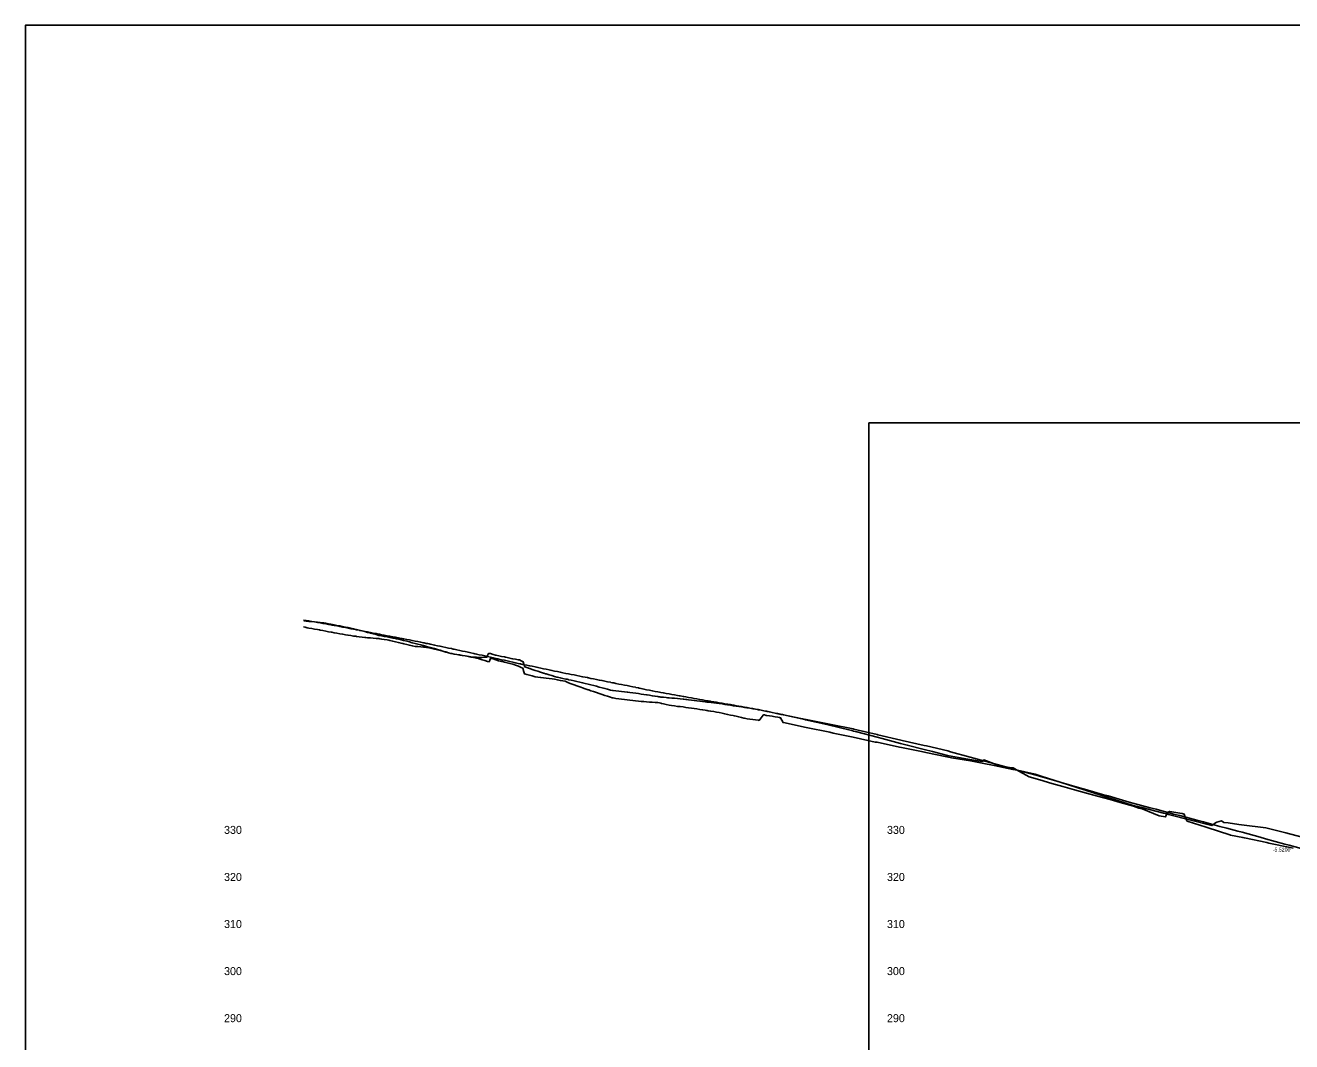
# Model space of a CAD drawing. Extents: x 2230305 to 2233905, y 1078764 to 1080964.
# Drawn here: x 2230305 to 2231649, y 1079884 to 1080964 of the extents above; entities that cross this region are included whole.
import ezdxf

# ---------------------------------------------------------------- set-up
doc = ezdxf.new("R2010")
doc.units = 0
for name, color, linetype in [('BR_EXIST_GROUND_LT', 7, 'Continuous'), ('BR_EXIST_GROUND_RT', 7, 'Continuous'), ('BR_USER NOTES', 7, 'Continuous'), ('RD_DDB_ElevTX', 7, 'Continuous'), ('RD_DDB_Profile_EX', 7, 'Continuous'), ('RD_SHT_IplotShp', 7, 'Continuous'), ('RD_SHT_ShtClip', 7, 'Continuous')]:
    doc.layers.add(name, color=color, linetype=linetype)

msp = doc.modelspace()

# ---------------------------------------------------------------- linework, layer by layer
at = {"layer": 'BR_EXIST_GROUND_LT'}
msp.add_lwpolyline([(2230600.2, 1080324.6), (2230601.8, 1080324.3), (2230603, 1080324), (2230604, 1080323.8), (2230605.9, 1080323.4), (2230608.9, 1080322.9), (2230611.9, 1080322.3), (2230614.8, 1080321.9), (2230616.9, 1080321.5), (2230617.8, 1080321.3), (2230620.7, 1080320.7), (2230623.7, 1080320.2), (2230626.7, 1080319.6), (2230629.6, 1080319.1), (2230630.2, 1080319), (2230632.6, 1080318.5), (2230635.6, 1080317.9), (2230638.5, 1080317.4), (2230641.7, 1080316.8), (2230644.5, 1080316.4), (2230647.4, 1080315.9), (2230650.4, 1080315.4), (2230653.3, 1080315), (2230655.6, 1080314.7), (2230656.3, 1080314.6), (2230659.3, 1080314.2), (2230662.2, 1080313.8), (2230665.2, 1080313.5), (2230666.2, 1080313.4), (2230668.2, 1080313.2), (2230671.1, 1080312.9), (2230674.1, 1080312.6), (2230677.1, 1080312.4), (2230680, 1080312.2), (2230681.1, 1080312.1), (2230683, 1080311.8), (2230685.9, 1080311.3), (2230688.9, 1080310.9), (2230690.7, 1080310.6), (2230691.9, 1080310.3), (2230694.8, 1080309.5), (2230697.8, 1080308.8), (2230700.8, 1080308), (2230703.7, 1080307.3), (2230705.4, 1080306.9), (2230706.7, 1080306.6), (2230709.7, 1080305.9), (2230712.6, 1080305.2), (2230715.6, 1080304.6), (2230718.5, 1080304), (2230721.5, 1080303.7), (2230724.5, 1080303.4), (2230727.4, 1080303.2), (2230730.4, 1080303), (2230730.9, 1080302.9), (2230731.4, 1080302.8), (2230733.4, 1080302.3), (2230736.3, 1080301.7), (2230739.3, 1080301), (2230742.3, 1080300.4), (2230745.2, 1080299.7), (2230746.4, 1080299.5), (2230748.2, 1080298.9), (2230751.1, 1080298), (2230754.1, 1080297.2), (2230757.1, 1080296.3), (2230760, 1080295.8), (2230763, 1080295.3), (2230766, 1080294.9), (2230768.9, 1080294.4), (2230771.9, 1080294), (2230773.7, 1080293.7), (2230774.9, 1080293.4), (2230777.8, 1080292.7), (2230780.8, 1080292), (2230782.3, 1080291.7), (2230783.8, 1080291.4), (2230785.8, 1080291), (2230786.7, 1080290.8), (2230789.7, 1080289.8), (2230792.6, 1080289), (2230795.6, 1080288.1), (2230797.1, 1080287.7), (2230798.5, 1080291.2), (2230799.9, 1080291.2), (2230801.5, 1080290.7), (2230804.5, 1080289.6), (2230807.1, 1080288.8), (2230807.5, 1080288.7), (2230810.4, 1080288), (2230811.3, 1080287.8), (2230813.4, 1080287.3), (2230816.4, 1080286.5), (2230819.3, 1080285.7), (2230822.3, 1080285), (2230823.6, 1080284.6), (2230825.2, 1080284.1), (2230828.3, 1080283), (2230831.2, 1080281.7), (2230833.1, 1080280.9), (2230834.1, 1080277.1), (2230834.8, 1080274.7), (2230837.1, 1080274.1), (2230840.1, 1080273.3), (2230843, 1080272.6), (2230846.1, 1080271.8), (2230849, 1080271.4), (2230851.9, 1080271), (2230852.2, 1080270.9), (2230854.9, 1080270.6), (2230857.8, 1080270.2), (2230860.8, 1080269.8), (2230864.1, 1080269.5), (2230866.7, 1080269), (2230869.7, 1080268.4), (2230872.7, 1080267.9), (2230875.6, 1080267.3), (2230878, 1080266.9), (2230878.6, 1080266.6), (2230881.6, 1080265.4), (2230884.5, 1080264.3), (2230887.5, 1080263.1), (2230890.4, 1080262), (2230893.4, 1080260.9), (2230894.6, 1080260.5), (2230896.4, 1080259.9), (2230899.3, 1080258.9), (2230902.3, 1080258), (2230903.2, 1080257.7), (2230905.3, 1080256.9), (2230908.2, 1080255.9), (2230911.2, 1080254.9), (2230914.2, 1080253.9), (2230917.1, 1080252.9), (2230920.1, 1080251.9), (2230923, 1080251), (2230926, 1080250.1), (2230927.8, 1080249.5), (2230928.5, 1080249.3), (2230929, 1080249.3), (2230931.9, 1080248.8), (2230934.9, 1080248.3), (2230937.8, 1080247.9), (2230940.8, 1080247.6), (2230943.8, 1080247.2), (2230946.8, 1080246.9), (2230949.7, 1080246.5), (2230952.8, 1080246.1), (2230955.7, 1080245.8), (2230958.6, 1080245.5), (2230961.6, 1080245.3), (2230964.5, 1080245), (2230967.5, 1080244.8), (2230970.5, 1080244.6), (2230973.4, 1080244.4), (2230976.4, 1080244.2), (2230978.1, 1080244.1), (2230979.4, 1080243.7), (2230980.4, 1080243.4), (2230982.3, 1080243), (2230985.3, 1080242.3), (2230988.3, 1080241.7), (2230991, 1080241.1), (2230994.2, 1080240.7), (2230997.1, 1080240.3), (2231000.1, 1080240), (2231003.1, 1080239.6), (2231006, 1080239.2), (2231009, 1080238.8), (2231012, 1080238.4), (2231014.9, 1080238), (2231017.9, 1080237.5), (2231020.9, 1080237.1), (2231023.8, 1080236.6), (2231024.3, 1080236.6), (2231026.8, 1080236.2), (2231028.2, 1080236), (2231028.7, 1080235.9), (2231029.7, 1080235.7), (2231032.2, 1080235.2), (2231032.7, 1080235.2), (2231035.9, 1080234.7), (2231038.6, 1080234.2), (2231041.6, 1080233.6), (2231044.6, 1080233), (2231047.5, 1080232.3), (2231050.5, 1080231.7), (2231053.5, 1080231), (2231056.4, 1080230.4), (2231057.7, 1080230.1), (2231059.4, 1080229.8), (2231062.3, 1080229), (2231065.3, 1080228.3), (2231067.8, 1080227.6), (2231068.3, 1080227.6), (2231071.2, 1080227.1), (2231074.2, 1080226.7), (2231077.2, 1080226.3), (2231080.1, 1080225.9), (2231083.1, 1080225.5), (2231083.9, 1080225.4), (2231086.1, 1080228.2), (2231088.2, 1080231), (2231089, 1080231.2), (2231089.8, 1080231.4), (2231091.4, 1080230.7), (2231092, 1080230.6), (2231094.9, 1080230.2), (2231097.9, 1080229.7), (2231099.3, 1080229.5), (2231100.9, 1080229.2), (2231103.8, 1080228.7), (2231105.7, 1080228.4), (2231106.1, 1080228.1), (2231106.8, 1080228.2), (2231109.3, 1080223.1), (2231109.8, 1080223), (2231134, 1080217.9), (2231158.9, 1080212.7), (2231162.5, 1080211.9), (2231183.9, 1080207.5), (2231207.1, 1080202.4), (2231208.2, 1080202.3), (2231209.2, 1080202.1), (2231233.1, 1080197), (2231235, 1080196.6), (2231258.1, 1080191.8), (2231260.8, 1080191.3), (2231283.2, 1080186.6), (2231283.5, 1080186.5), (2231288.2, 1080185.6), (2231308.5, 1080182.3), (2231320.9, 1080179.8), (2231333.5, 1080177.6), (2231353.2, 1080173.3), (2231358.4, 1080172.4), (2231377.2, 1080168.2), (2231383.4, 1080166.2), (2231404.8, 1080159.5), (2231429.2, 1080151.7), (2231429.9, 1080151.5), (2231431.1, 1080151), (2231455.7, 1080143.2), (2231480, 1080135.4), (2231490.4, 1080132.8), (2231513.5, 1080126.8), (2231517, 1080126), (2231518.7, 1080125.5), (2231542.3, 1080119.4), (2231564.8, 1080113.7), (2231568.6, 1080116.5), (2231569.9, 1080117.4), (2231575.1, 1080118.8), (2231577.5, 1080116.8), (2231582.1, 1080116.4), (2231593.4, 1080114.9), (2231596.1, 1080114.6), (2231621.9, 1080111.4), (2231643.1, 1080106), (2231647, 1080104.8), (2231665, 1080100.1)], dxfattribs=at)
at = {"layer": 'BR_EXIST_GROUND_RT'}
msp.add_lwpolyline([(2230600.6, 1080331.1), (2230603, 1080330.9), (2230604.4, 1080330.7), (2230605.9, 1080330.5), (2230608.9, 1080330.3), (2230611.9, 1080330), (2230614.8, 1080329.7), (2230617.8, 1080329.4), (2230620.7, 1080329), (2230621.8, 1080328.9), (2230623.7, 1080328.6), (2230626.7, 1080328), (2230628.9, 1080327.6), (2230629.6, 1080327.4), (2230630.3, 1080327.3), (2230630.8, 1080327.2), (2230632.6, 1080326.9), (2230635.6, 1080326.3), (2230638.5, 1080325.8), (2230639.6, 1080325.6), (2230641.5, 1080325.1), (2230644.5, 1080324.5), (2230647.4, 1080323.9), (2230650.4, 1080323.2), (2230653.3, 1080322.5), (2230655.3, 1080322), (2230656.3, 1080321.8), (2230659.3, 1080321.1), (2230662.2, 1080320.4), (2230665.2, 1080319.7), (2230668.2, 1080318.9), (2230669.4, 1080318.6), (2230671.1, 1080318.2), (2230674.1, 1080317.4), (2230677.1, 1080316.5), (2230680, 1080315.7), (2230680.5, 1080315.6), (2230681.6, 1080315.4), (2230683, 1080315.2), (2230685.9, 1080314.6), (2230688.9, 1080314), (2230691.9, 1080313.4), (2230694.8, 1080312.8), (2230697.8, 1080312.2), (2230699, 1080311.9), (2230700.8, 1080311.5), (2230703.7, 1080310.8), (2230706.2, 1080310.2), (2230706.7, 1080310.1), (2230709.7, 1080309.4), (2230712.6, 1080308.7), (2230715.6, 1080307.9), (2230718.5, 1080307.2), (2230721.5, 1080306.4), (2230724.5, 1080305.7), (2230726.8, 1080305), (2230727.4, 1080304.9), (2230730.7, 1080303.9), (2230733, 1080303.3), (2230733.4, 1080303.2), (2230736.3, 1080302.4), (2230739.3, 1080301.6), (2230742.3, 1080300.8), (2230745.2, 1080299.9), (2230748.2, 1080299), (2230751.1, 1080298.1), (2230754.1, 1080297.2), (2230756.7, 1080296.4), (2230757.1, 1080296.4), (2230757.5, 1080296.3), (2230760, 1080295.8), (2230763, 1080295.3), (2230766, 1080294.8), (2230768.9, 1080294.3), (2230771.9, 1080293.8), (2230774.9, 1080293.4), (2230776, 1080293.2), (2230777.8, 1080292.9), (2230780.8, 1080292.6), (2230782.1, 1080292.4), (2230783.8, 1080292.4), (2230786.7, 1080292.3), (2230788.3, 1080292.2), (2230789.7, 1080292.3), (2230792.6, 1080292.4), (2230794.9, 1080292.6), (2230795.6, 1080294.2), (2230796.5, 1080296.3), (2230798.3, 1080296.4), (2230798.6, 1080296.3), (2230801.5, 1080295.5), (2230803.8, 1080294.8), (2230804.5, 1080294.7), (2230807.5, 1080294), (2230810.4, 1080293.4), (2230813.4, 1080292.8), (2230814.5, 1080292.5), (2230816.4, 1080292.1), (2230819.3, 1080291.3), (2230820.6, 1080291), (2230822.3, 1080290.7), (2230825.2, 1080290.3), (2230828.2, 1080289.8), (2230829.3, 1080289.6), (2230831.2, 1080288.7), (2230833.2, 1080287.7), (2230834.1, 1080285), (2230835.1, 1080282.3), (2230837.1, 1080281.6), (2230840.1, 1080280.5), (2230840.4, 1080280.4), (2230843, 1080279.5), (2230846, 1080278.5), (2230849, 1080277.5), (2230851.9, 1080276.6), (2230854.9, 1080275.6), (2230855.4, 1080275.5), (2230857.2, 1080274.9), (2230857.8, 1080274.7), (2230860.8, 1080273.8), (2230863.8, 1080272.9), (2230866.7, 1080272.1), (2230869, 1080271.4), (2230869.7, 1080271.3), (2230872.7, 1080270.6), (2230875.6, 1080269.9), (2230878.6, 1080269.3), (2230879.9, 1080269), (2230881.1, 1080268.7), (2230881.6, 1080268.6), (2230884.5, 1080268), (2230887.5, 1080267.3), (2230890.4, 1080266.6), (2230893.4, 1080266), (2230896.4, 1080265.3), (2230899.3, 1080264.6), (2230902.3, 1080263.9), (2230903.7, 1080263.5), (2230905.3, 1080263.1), (2230908.4, 1080262.3), (2230911.2, 1080261.6), (2230914.2, 1080260.8), (2230917.1, 1080260), (2230920.1, 1080259.3), (2230923, 1080258.5), (2230926, 1080257.6), (2230928.4, 1080257), (2230929, 1080257), (2230931.9, 1080256.7), (2230934.9, 1080256.4), (2230937.9, 1080256.1), (2230940.8, 1080255.7), (2230943.8, 1080255.4), (2230944.4, 1080255.3), (2230946.8, 1080255), (2230949.7, 1080254.6), (2230952.9, 1080254.2), (2230955.7, 1080253.8), (2230958.6, 1080253.4), (2230961.6, 1080253), (2230964.5, 1080252.6), (2230964.9, 1080252.5), (2230967.5, 1080252.1), (2230970.5, 1080251.6), (2230973.4, 1080251.1), (2230976.4, 1080250.6), (2230977.4, 1080250.4), (2230978.6, 1080250.3), (2230979.4, 1080250.2), (2230982.3, 1080250), (2230985.3, 1080249.7), (2230986.8, 1080249.5), (2230988.3, 1080249.4), (2230991.2, 1080249.1), (2230994.2, 1080248.9), (2230997.1, 1080248.6), (2231000.1, 1080248.3), (2231003.1, 1080247.9), (2231004, 1080247.9), (2231006, 1080247.6), (2231007.3, 1080247.5), (2231009, 1080247.3), (2231012, 1080246.9), (2231014.9, 1080246.6), (2231017.9, 1080246.2), (2231020.9, 1080245.8), (2231023.8, 1080245.4), (2231026.8, 1080245.1), (2231028.5, 1080244.8), (2231028.9, 1080244.8), (2231029.7, 1080244.7), (2231032.9, 1080244.3), (2231033.9, 1080244.2), (2231035.7, 1080244), (2231038.6, 1080243.7), (2231039.3, 1080243.6), (2231041.6, 1080243.2), (2231044.6, 1080242.8), (2231047.5, 1080242.3), (2231050.5, 1080241.9), (2231053.5, 1080241.4), (2231056.4, 1080241), (2231057.1, 1080240.9), (2231057.8, 1080240.8), (2231059.4, 1080240.5), (2231062.3, 1080240.1), (2231065.3, 1080239.6), (2231068.3, 1080239.2), (2231071.2, 1080238.7), (2231074.2, 1080238.3), (2231077.2, 1080237.8), (2231080.1, 1080237.3), (2231082, 1080237.1), (2231083.1, 1080236.8), (2231086.1, 1080236.2), (2231089, 1080235.5), (2231092, 1080234.9), (2231094.9, 1080234.3), (2231097.9, 1080233.6), (2231100.9, 1080233), (2231103.8, 1080232.4), (2231107.1, 1080231.7), (2231109.8, 1080231.1), (2231132.3, 1080226.3), (2231133.1, 1080226.1), (2231155.8, 1080220.9), (2231157.3, 1080220.5), (2231179.3, 1080215.4), (2231182.3, 1080214.6), (2231184.3, 1080214.1), (2231187.8, 1080213.2), (2231209.2, 1080207.5), (2231214.6, 1080206.2), (2231234.2, 1080201), (2231241.3, 1080199.2), (2231259.2, 1080194.5), (2231267.9, 1080192.3), (2231284.1, 1080188), (2231288, 1080187.3), (2231295.5, 1080186), (2231305.5, 1080184.3), (2231320.6, 1080181.7), (2231321.6, 1080182.2), (2231322.7, 1080183.5), (2231335.6, 1080178.5), (2231342.4, 1080176.6), (2231349.6, 1080175.5), (2231353.6, 1080174.8), (2231357.1, 1080172.8), (2231370.7, 1080165.4), (2231382.1, 1080162.1), (2231394.9, 1080158.4), (2231406.6, 1080155.2), (2231418.9, 1080151.7), (2231431.6, 1080148.2), (2231443.1, 1080145), (2231456.6, 1080141.2), (2231467.2, 1080138.2), (2231481.5, 1080134.3), (2231487, 1080132.1), (2231490.8, 1080131.4), (2231508.8, 1080124), (2231515.6, 1080122.8), (2231517.7, 1080127.7), (2231518.1, 1080127.9), (2231519.9, 1080128.6), (2231522.2, 1080128.2), (2231530.6, 1080126.9), (2231533.2, 1080126.6), (2231534.3, 1080126.1), (2231535.3, 1080125.9), (2231536.7, 1080121.6), (2231538.6, 1080118.5), (2231558.6, 1080111.9), (2231559.6, 1080111.7), (2231583.7, 1080103.8), (2231584.4, 1080103.6), (2231597.6, 1080100.9), (2231598.1, 1080100.8), (2231599.3, 1080100.5), (2231623, 1080095.6), (2231625.2, 1080095.1), (2231648, 1080090.3), (2231651.1, 1080089.7)], dxfattribs=at)
at = {"layer": 'RD_DDB_Profile_EX'}
msp.add_lwpolyline([(2230600, 1080332), (2230603, 1080331.5), (2230604.3, 1080331.3), (2230605.9, 1080331), (2230608.9, 1080330.5), (2230611.9, 1080330), (2230614.8, 1080329.4), (2230617.8, 1080328.9), (2230620.7, 1080328.4), (2230623.7, 1080327.9), (2230626.7, 1080327.3), (2230629.6, 1080326.8), (2230630.6, 1080326.6), (2230632.6, 1080326.2), (2230635.6, 1080325.7), (2230638.5, 1080325.1), (2230641.5, 1080324.5), (2230644.5, 1080324), (2230647.4, 1080323.4), (2230650.4, 1080322.8), (2230653.3, 1080322.3), (2230655.5, 1080321.8), (2230656.3, 1080321.7), (2230659.3, 1080321.1), (2230659.7, 1080321), (2230662.2, 1080320.5), (2230665.2, 1080319.9), (2230668.2, 1080319.3), (2230671.1, 1080318.8), (2230674.1, 1080318.2), (2230677.1, 1080317.6), (2230679.3, 1080317.1), (2230680, 1080317), (2230680.8, 1080316.8), (2230683, 1080316.4), (2230685.9, 1080315.9), (2230688.9, 1080315.3), (2230691.9, 1080314.7), (2230694.8, 1080314.2), (2230697.8, 1080313.6), (2230700.8, 1080313.1), (2230703.7, 1080312.5), (2230704.5, 1080312.4), (2230705.8, 1080312.1), (2230706.7, 1080311.9), (2230709.7, 1080311.3), (2230712.6, 1080310.8), (2230715.6, 1080310.2), (2230718.5, 1080309.6), (2230721.5, 1080309), (2230724.5, 1080308.4), (2230727.4, 1080307.9), (2230728.3, 1080307.7), (2230730.4, 1080307.2), (2230730.8, 1080307.1), (2230732.2, 1080306.9), (2230733.4, 1080306.6), (2230734.6, 1080306.3), (2230736.3, 1080306), (2230739.3, 1080305.4), (2230742.3, 1080304.7), (2230745.2, 1080304.1), (2230748.2, 1080303.5), (2230751.1, 1080302.9), (2230754.1, 1080302.2), (2230757.1, 1080301.6), (2230759, 1080301.2), (2230760, 1080301), (2230763, 1080300.3), (2230766, 1080299.7), (2230768.9, 1080299), (2230771.9, 1080298.4), (2230774.9, 1080297.7), (2230777.8, 1080297.1), (2230780.8, 1080296.4), (2230782.1, 1080296.1), (2230783.8, 1080295.8), (2230786.7, 1080295.1), (2230789.7, 1080294.5), (2230792.6, 1080293.8), (2230795.6, 1080293.2), (2230798.6, 1080292.5), (2230801.5, 1080291.9), (2230804.5, 1080291.2), (2230805.6, 1080290.9), (2230806.4, 1080290.8), (2230807.5, 1080290.5), (2230810.4, 1080289.8), (2230813.4, 1080289.2), (2230816.4, 1080288.5), (2230819.3, 1080287.8), (2230822.3, 1080287.2), (2230825.2, 1080286.5), (2230828.2, 1080285.8), (2230830, 1080285.4), (2230830.5, 1080285.3), (2230831.2, 1080285.1), (2230834.1, 1080284.5), (2230837.1, 1080284), (2230840.1, 1080283.4), (2230843, 1080282.8), (2230846, 1080282.2), (2230849, 1080281.6), (2230852.1, 1080280.9), (2230853.5, 1080280.6), (2230854.9, 1080280.3), (2230857.8, 1080279.7), (2230860.8, 1080279.1), (2230863.8, 1080278.5), (2230866.7, 1080277.8), (2230869.7, 1080277.2), (2230872.7, 1080276.6), (2230875.6, 1080275.9), (2230878.5, 1080275.3), (2230878.5, 1080275.3), (2230881.6, 1080274.7), (2230884.5, 1080274.1), (2230887.5, 1080273.6), (2230890.4, 1080273), (2230893.4, 1080272.4), (2230896.4, 1080271.8), (2230899.3, 1080271.2), (2230901.5, 1080270.8), (2230902.3, 1080270.6), (2230902.9, 1080270.5), (2230905.3, 1080270), (2230908.2, 1080269.4), (2230911.2, 1080268.8), (2230914.2, 1080268.2), (2230917.1, 1080267.6), (2230920.1, 1080267), (2230923, 1080266.4), (2230926, 1080265.8), (2230926.4, 1080265.7), (2230928.1, 1080265.4), (2230929, 1080265.2), (2230929.8, 1080265.1), (2230931.9, 1080264.6), (2230934.9, 1080264), (2230937.9, 1080263.4), (2230940.8, 1080262.9), (2230943.8, 1080262.3), (2230946.8, 1080261.7), (2230949.7, 1080261.1), (2230952.7, 1080260.5), (2230953.1, 1080260.4), (2230955.7, 1080259.8), (2230956.7, 1080259.6), (2230958.6, 1080259.2), (2230961.6, 1080258.6), (2230964.5, 1080258), (2230967.5, 1080257.4), (2230970.5, 1080256.8), (2230973.4, 1080256.2), (2230976.4, 1080255.6), (2230978.3, 1080255.2), (2230979.4, 1080255), (2230982.3, 1080254.5), (2230985.3, 1080254), (2230988.3, 1080253.5), (2230991.2, 1080252.9), (2230994.2, 1080252.4), (2230997.1, 1080251.9), (2230999, 1080251.6), (2231000.1, 1080251.4), (2231003.1, 1080250.9), (2231004.1, 1080250.7), (2231006, 1080250.4), (2231009, 1080249.8), (2231012, 1080249.3), (2231014.9, 1080248.8), (2231017.9, 1080248.2), (2231020.9, 1080247.7), (2231023.8, 1080247.2), (2231026.8, 1080246.6), (2231029.1, 1080246.2), (2231029.8, 1080246.1), (2231032.1, 1080245.7), (2231032.7, 1080245.6), (2231035.7, 1080245.1), (2231038.6, 1080244.6), (2231041.6, 1080244.1), (2231044.6, 1080243.6), (2231047.5, 1080243.1), (2231050.6, 1080242.6), (2231053.5, 1080242.1), (2231056.4, 1080241.5), (2231057.1, 1080241.4), (2231059.4, 1080241), (2231062.3, 1080240.5), (2231065.3, 1080240), (2231068.3, 1080239.5), (2231071.2, 1080238.9), (2231074.2, 1080238.4), (2231076, 1080238.1), (2231077.2, 1080237.9), (2231080.1, 1080237.3), (2231082.1, 1080237), (2231083.3, 1080236.7), (2231083.9, 1080236.6), (2231086.1, 1080236.2), (2231089, 1080235.6), (2231092, 1080235), (2231094.9, 1080234.4), (2231097.9, 1080233.8), (2231100.9, 1080233.2), (2231103.8, 1080232.6), (2231106.8, 1080231.9), (2231108.8, 1080231.5), (2231109.8, 1080231.3), (2231130.1, 1080227.2), (2231133.8, 1080226.4), (2231156.8, 1080221.7), (2231158.7, 1080221.3), (2231183.7, 1080216.3), (2231184.5, 1080216.1), (2231209.4, 1080210.3), (2231210.1, 1080210.1), (2231234.3, 1080204.5), (2231235.8, 1080204.1), (2231259.3, 1080198.7), (2231261.6, 1080198.2), (2231284.3, 1080192.9), (2231287.1, 1080192.1), (2231308, 1080186.3), (2231329.1, 1080180.5), (2231333, 1080179.5), (2231353.6, 1080173.8), (2231358, 1080172.6), (2231378.1, 1080167.1), (2231382.9, 1080165.7), (2231400.1, 1080160.8), (2231404.6, 1080159.5), (2231424.1, 1080153.9), (2231429.6, 1080152.3), (2231448.7, 1080146.8), (2231454.6, 1080145.1), (2231473.3, 1080139.7), (2231479.5, 1080137.9), (2231480.8, 1080137.5), (2231499.3, 1080132.5), (2231505.7, 1080130.9), (2231524, 1080125.9), (2231530.7, 1080124.2), (2231548.6, 1080119.4), (2231555.7, 1080117.6), (2231573.3, 1080112.8), (2231580.6, 1080110.9), (2231592.4, 1080107.7), (2231596.8, 1080106.5), (2231616, 1080101.2), (2231621.8, 1080099.6), (2231642.1, 1080094), (2231646.7, 1080092.7), (2231668.3, 1080086.7)], dxfattribs=at)
at = {"layer": 'RD_SHT_IplotShp'}
msp.add_lwpolyline([(2230304.7, 1078763.7), (2233904.7, 1078763.7), (2233904.7, 1080963.7), (2230304.7, 1080963.7)], close=True, dxfattribs=at)
at = {"layer": 'RD_SHT_ShtClip'}
msp.add_lwpolyline([(2233000.6, 1079441.3), (2231200.6, 1079441.3), (2231200.6, 1080541.3), (2233000.6, 1080541.3)], close=True, dxfattribs=at)

# ---------------------------------------------------------------- texts
at = {"layer": 'BR_USER NOTES'}
msp.add_text('-5.5200', height=4, dxfattribs=at).set_placement((2231629.4, 1080086.1))
at = {"layer": 'RD_DDB_ElevTX'}
for s, p in [('330', (2230515.7, 1080104.8)), ('330', (2231219.7, 1080104.8)), ('320', (2230515.7, 1080054.8)), ('320', (2231219.7, 1080054.8)), ('310', (2230515.7, 1080004.8)), ('310', (2231219.7, 1080004.8)), ('300', (2230515.7, 1079954.8)), ('300', (2231219.7, 1079954.8)), ('290', (2230515.7, 1079904.8)), ('290', (2231219.7, 1079904.8))]:
    msp.add_text(s, height=8.5, dxfattribs=at).set_placement(p)

doc.saveas('drawing.dxf')
